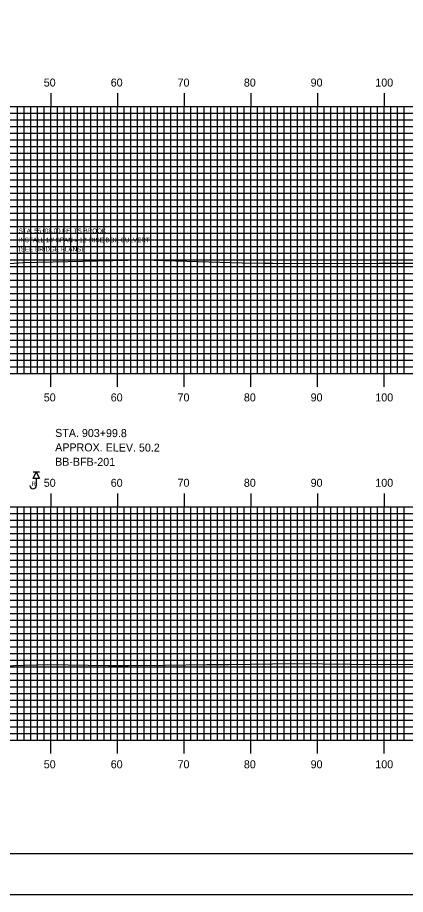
# Model space of a CAD drawing. Extents: x 857110 to 857453, y 364765 to 364985.
# Drawn here: x 857320.8 to 857379, y 364765.2 to 364896.6 of the extents above; entities that cross this region are included whole.
import ezdxf

# ---------------------------------------------------------------- set-up
doc = ezdxf.new("R2010")
doc.units = 0
for name, color, linetype in [('ANNOTATION', 7, 'Continuous'), ('BORDER', 7, 'Continuous'), ('BORING - REFUSAL', 7, 'Continuous'), ('H_V ANNOTATION', 7, 'Continuous'), ('MAJOR', 7, 'Continuous'), ('MINOR', 7, 'Continuous'), ('PLOT BOUNDARY', 7, 'Continuous'), ('S_Roadway_Centerline', 7, 'Continuous')]:
    doc.layers.add(name, color=color, linetype=linetype)

msp = doc.modelspace()

# ---------------------------------------------------------------- linework, layer by layer
at = {"layer": 'BORDER'}
msp.add_lwpolyline([(857126.19, 364771.3), (857446.19, 364771.3), (857446.19, 364981.3), (857126.19, 364981.3)], close=True, dxfattribs=at)
at = {"layer": 'BORING - REFUSAL'}
for p, q in [((857324.07, 364828.5), (857323.11, 364828.5)), ((857323.59, 364827.54), (857323.59, 364826.48))]:
    msp.add_line(p, q, dxfattribs=at)
msp.add_lwpolyline([(857323.59, 364828.5), (857324.07, 364827.54), (857323.11, 364827.54)], close=True, dxfattribs=at)
msp.add_arc((857323.11, 364826.48), 0.485, 180, 0, dxfattribs=at)
at = {"layer": 'MAJOR'}
for p, q in [((857325.79, 364885.31), (857325.79, 364883.3)), ((857335.79, 364885.31), (857335.79, 364883.3)), ((857345.79, 364885.31), (857345.79, 364883.3)), ((857355.79, 364885.31), (857355.79, 364883.3)), ((857365.79, 364885.31), (857365.79, 364883.3)), ((857375.79, 364885.31), (857375.79, 364883.3)), ((857135.79, 364883.3), (857415.79, 364883.3)), ((857135.79, 364883.3), (857415.79, 364883.3)), ((857325.79, 364843.3), (857325.79, 364883.3)), ((857335.79, 364843.3), (857335.79, 364883.3)), ((857345.79, 364843.3), (857345.79, 364883.3)), ((857355.79, 364843.3), (857355.79, 364883.3)), ((857365.79, 364843.3), (857365.79, 364883.3)), ((857375.79, 364843.3), (857375.79, 364883.3)), ((857135.79, 364878.3), (857415.79, 364878.3)), ((857135.79, 364873.3), (857415.79, 364873.3)), ((857135.79, 364868.3), (857415.79, 364868.3)), ((857135.79, 364863.3), (857415.79, 364863.3)), ((857135.79, 364858.3), (857415.79, 364858.3)), ((857135.79, 364853.3), (857415.79, 364853.3)), ((857135.79, 364848.3), (857415.79, 364848.3)), ((857135.79, 364843.3), (857415.79, 364843.3)), ((857135.79, 364843.3), (857415.79, 364843.3)), ((857325.79, 364841.3), (857325.79, 364843.3)), ((857335.79, 364841.3), (857335.79, 364843.3)), ((857345.79, 364841.3), (857345.79, 364843.3)), ((857355.79, 364841.3), (857355.79, 364843.3)), ((857365.79, 364841.3), (857365.79, 364843.3)), ((857375.79, 364841.3), (857375.79, 364843.3)), ((857325.79, 364825.31), (857325.79, 364823.3)), ((857335.79, 364825.31), (857335.79, 364823.3)), ((857345.79, 364825.31), (857345.79, 364823.3)), ((857355.79, 364825.31), (857355.79, 364823.3)), ((857365.79, 364825.31), (857365.79, 364823.3)), ((857375.79, 364825.31), (857375.79, 364823.3)), ((857135.79, 364823.3), (857415.79, 364823.3)), ((857135.79, 364823.3), (857415.79, 364823.3)), ((857325.79, 364788.3), (857325.79, 364823.3)), ((857335.79, 364788.3), (857335.79, 364823.3)), ((857345.79, 364788.3), (857345.79, 364823.3)), ((857355.79, 364788.3), (857355.79, 364823.3)), ((857365.79, 364788.3), (857365.79, 364823.3)), ((857375.79, 364788.3), (857375.79, 364823.3)), ((857135.79, 364818.3), (857415.79, 364818.3)), ((857135.79, 364813.3), (857415.79, 364813.3)), ((857135.79, 364808.3), (857415.79, 364808.3)), ((857135.79, 364803.3), (857415.79, 364803.3)), ((857135.79, 364798.3), (857415.79, 364798.3)), ((857135.79, 364793.3), (857415.79, 364793.3)), ((857135.79, 364788.3), (857415.79, 364788.3)), ((857135.79, 364788.3), (857415.79, 364788.3)), ((857325.79, 364786.3), (857325.79, 364788.3)), ((857335.79, 364786.3), (857335.79, 364788.3)), ((857345.79, 364786.3), (857345.79, 364788.3)), ((857355.79, 364786.3), (857355.79, 364788.3)), ((857365.79, 364786.3), (857365.79, 364788.3)), ((857375.79, 364786.3), (857375.79, 364788.3))]:
    msp.add_line(p, q, dxfattribs=at)
at = {"layer": 'MINOR'}
for p, q in [((857320.79, 364843.3), (857320.79, 364883.3)), ((857321.79, 364843.3), (857321.79, 364883.3)), ((857322.79, 364843.3), (857322.79, 364883.3)), ((857323.79, 364843.3), (857323.79, 364883.3)), ((857324.79, 364843.3), (857324.79, 364883.3)), ((857326.79, 364843.3), (857326.79, 364883.3)), ((857327.79, 364843.3), (857327.79, 364883.3)), ((857328.79, 364843.3), (857328.79, 364883.3)), ((857329.79, 364843.3), (857329.79, 364883.3)), ((857330.79, 364843.3), (857330.79, 364883.3)), ((857331.79, 364843.3), (857331.79, 364883.3)), ((857332.79, 364843.3), (857332.79, 364883.3)), ((857333.79, 364843.3), (857333.79, 364883.3)), ((857334.79, 364843.3), (857334.79, 364883.3)), ((857336.79, 364843.3), (857336.79, 364883.3)), ((857337.79, 364843.3), (857337.79, 364883.3)), ((857338.79, 364843.3), (857338.79, 364883.3)), ((857339.79, 364843.3), (857339.79, 364883.3)), ((857340.79, 364843.3), (857340.79, 364883.3)), ((857341.79, 364843.3), (857341.79, 364883.3)), ((857342.79, 364843.3), (857342.79, 364883.3)), ((857343.79, 364843.3), (857343.79, 364883.3)), ((857344.79, 364843.3), (857344.79, 364883.3)), ((857346.79, 364843.3), (857346.79, 364883.3)), ((857347.79, 364843.3), (857347.79, 364883.3)), ((857348.79, 364843.3), (857348.79, 364883.3)), ((857349.79, 364843.3), (857349.79, 364883.3)), ((857350.79, 364843.3), (857350.79, 364883.3)), ((857351.79, 364843.3), (857351.79, 364883.3)), ((857352.79, 364843.3), (857352.79, 364883.3)), ((857353.79, 364843.3), (857353.79, 364883.3)), ((857354.79, 364843.3), (857354.79, 364883.3)), ((857356.79, 364843.3), (857356.79, 364883.3)), ((857357.79, 364843.3), (857357.79, 364883.3)), ((857358.79, 364843.3), (857358.79, 364883.3)), ((857359.79, 364843.3), (857359.79, 364883.3)), ((857360.79, 364843.3), (857360.79, 364883.3)), ((857361.79, 364843.3), (857361.79, 364883.3)), ((857362.79, 364843.3), (857362.79, 364883.3)), ((857363.79, 364843.3), (857363.79, 364883.3)), ((857364.79, 364843.3), (857364.79, 364883.3)), ((857366.79, 364843.3), (857366.79, 364883.3)), ((857367.79, 364843.3), (857367.79, 364883.3)), ((857368.79, 364843.3), (857368.79, 364883.3)), ((857369.79, 364843.3), (857369.79, 364883.3)), ((857370.79, 364843.3), (857370.79, 364883.3)), ((857371.79, 364843.3), (857371.79, 364883.3)), ((857372.79, 364843.3), (857372.79, 364883.3)), ((857373.79, 364843.3), (857373.79, 364883.3)), ((857374.79, 364843.3), (857374.79, 364883.3)), ((857376.79, 364843.3), (857376.79, 364883.3)), ((857377.79, 364843.3), (857377.79, 364883.3)), ((857378.79, 364843.3), (857378.79, 364883.3)), ((857135.79, 364882.3), (857415.79, 364882.3)), ((857135.79, 364881.3), (857415.79, 364881.3)), ((857135.79, 364880.3), (857415.79, 364880.3)), ((857135.79, 364879.3), (857415.79, 364879.3)), ((857135.79, 364877.3), (857415.79, 364877.3)), ((857135.79, 364876.3), (857415.79, 364876.3)), ((857135.79, 364875.3), (857415.79, 364875.3)), ((857135.79, 364874.3), (857415.79, 364874.3)), ((857135.79, 364872.3), (857415.79, 364872.3)), ((857135.79, 364871.3), (857415.79, 364871.3)), ((857135.79, 364870.3), (857415.79, 364870.3)), ((857135.79, 364869.3), (857415.79, 364869.3)), ((857135.79, 364867.3), (857415.79, 364867.3)), ((857135.79, 364866.3), (857415.79, 364866.3)), ((857135.79, 364865.3), (857415.79, 364865.3)), ((857135.79, 364864.3), (857415.79, 364864.3)), ((857135.79, 364862.3), (857415.79, 364862.3)), ((857135.79, 364861.3), (857415.79, 364861.3)), ((857135.79, 364860.3), (857415.79, 364860.3)), ((857135.79, 364859.3), (857415.79, 364859.3)), ((857135.79, 364857.3), (857415.79, 364857.3)), ((857135.79, 364856.3), (857415.79, 364856.3)), ((857135.79, 364855.3), (857415.79, 364855.3)), ((857135.79, 364854.3), (857415.79, 364854.3)), ((857135.79, 364852.3), (857415.79, 364852.3)), ((857135.79, 364851.3), (857415.79, 364851.3)), ((857135.79, 364850.3), (857415.79, 364850.3)), ((857135.79, 364849.3), (857415.79, 364849.3)), ((857135.79, 364847.3), (857415.79, 364847.3)), ((857135.79, 364846.3), (857415.79, 364846.3)), ((857135.79, 364845.3), (857415.79, 364845.3)), ((857135.79, 364844.3), (857415.79, 364844.3)), ((857135.79, 364822.3), (857415.79, 364822.3)), ((857320.79, 364788.3), (857320.79, 364823.3)), ((857321.79, 364788.3), (857321.79, 364823.3)), ((857322.79, 364788.3), (857322.79, 364823.3)), ((857323.79, 364788.3), (857323.79, 364823.3)), ((857324.79, 364788.3), (857324.79, 364823.3)), ((857326.79, 364788.3), (857326.79, 364823.3)), ((857327.79, 364788.3), (857327.79, 364823.3)), ((857328.79, 364788.3), (857328.79, 364823.3)), ((857329.79, 364788.3), (857329.79, 364823.3)), ((857330.79, 364788.3), (857330.79, 364823.3)), ((857331.79, 364788.3), (857331.79, 364823.3)), ((857332.79, 364788.3), (857332.79, 364823.3)), ((857333.79, 364788.3), (857333.79, 364823.3)), ((857334.79, 364788.3), (857334.79, 364823.3)), ((857336.79, 364788.3), (857336.79, 364823.3)), ((857337.79, 364788.3), (857337.79, 364823.3)), ((857338.79, 364788.3), (857338.79, 364823.3)), ((857339.79, 364788.3), (857339.79, 364823.3)), ((857340.79, 364788.3), (857340.79, 364823.3)), ((857341.79, 364788.3), (857341.79, 364823.3)), ((857342.79, 364788.3), (857342.79, 364823.3)), ((857343.79, 364788.3), (857343.79, 364823.3)), ((857344.79, 364788.3), (857344.79, 364823.3)), ((857346.79, 364788.3), (857346.79, 364823.3)), ((857347.79, 364788.3), (857347.79, 364823.3)), ((857348.79, 364788.3), (857348.79, 364823.3)), ((857349.79, 364788.3), (857349.79, 364823.3)), ((857350.79, 364788.3), (857350.79, 364823.3)), ((857351.79, 364788.3), (857351.79, 364823.3)), ((857352.79, 364788.3), (857352.79, 364823.3)), ((857353.79, 364788.3), (857353.79, 364823.3)), ((857354.79, 364788.3), (857354.79, 364823.3)), ((857356.79, 364788.3), (857356.79, 364823.3)), ((857357.79, 364788.3), (857357.79, 364823.3)), ((857358.79, 364788.3), (857358.79, 364823.3)), ((857359.79, 364788.3), (857359.79, 364823.3)), ((857360.79, 364788.3), (857360.79, 364823.3)), ((857361.79, 364788.3), (857361.79, 364823.3)), ((857362.79, 364788.3), (857362.79, 364823.3)), ((857363.79, 364788.3), (857363.79, 364823.3)), ((857364.79, 364788.3), (857364.79, 364823.3)), ((857366.79, 364788.3), (857366.79, 364823.3)), ((857367.79, 364788.3), (857367.79, 364823.3)), ((857368.79, 364788.3), (857368.79, 364823.3)), ((857369.79, 364788.3), (857369.79, 364823.3)), ((857370.79, 364788.3), (857370.79, 364823.3)), ((857371.79, 364788.3), (857371.79, 364823.3)), ((857372.79, 364788.3), (857372.79, 364823.3)), ((857373.79, 364788.3), (857373.79, 364823.3)), ((857374.79, 364788.3), (857374.79, 364823.3)), ((857376.79, 364788.3), (857376.79, 364823.3)), ((857377.79, 364788.3), (857377.79, 364823.3)), ((857378.79, 364788.3), (857378.79, 364823.3)), ((857135.79, 364821.3), (857415.79, 364821.3)), ((857135.79, 364820.3), (857415.79, 364820.3)), ((857135.79, 364819.3), (857415.79, 364819.3)), ((857135.79, 364817.3), (857415.79, 364817.3)), ((857135.79, 364816.3), (857415.79, 364816.3)), ((857135.79, 364815.3), (857415.79, 364815.3)), ((857135.79, 364814.3), (857415.79, 364814.3)), ((857135.79, 364812.3), (857415.79, 364812.3)), ((857135.79, 364811.3), (857415.79, 364811.3)), ((857135.79, 364810.3), (857415.79, 364810.3)), ((857135.79, 364809.3), (857415.79, 364809.3)), ((857135.79, 364807.3), (857415.79, 364807.3)), ((857135.79, 364806.3), (857415.79, 364806.3)), ((857135.79, 364805.3), (857415.79, 364805.3)), ((857135.79, 364804.3), (857415.79, 364804.3)), ((857135.79, 364802.3), (857415.79, 364802.3)), ((857135.79, 364801.3), (857415.79, 364801.3)), ((857135.79, 364800.3), (857415.79, 364800.3)), ((857135.79, 364799.3), (857415.79, 364799.3)), ((857135.79, 364797.3), (857415.79, 364797.3)), ((857135.79, 364796.3), (857415.79, 364796.3)), ((857135.79, 364795.3), (857415.79, 364795.3)), ((857135.79, 364794.3), (857415.79, 364794.3)), ((857135.79, 364792.3), (857415.79, 364792.3)), ((857135.79, 364791.3), (857415.79, 364791.3)), ((857135.79, 364790.3), (857415.79, 364790.3)), ((857135.79, 364789.3), (857415.79, 364789.3))]:
    msp.add_line(p, q, dxfattribs=at)
at = {"layer": 'PLOT BOUNDARY'}
msp.add_lwpolyline([(857110.01, 364765.18), (857450.01, 364765.18), (857450.01, 364985.18), (857110.01, 364985.18)], close=True, dxfattribs=at)
at = {"layer": 'S_Roadway_Centerline'}
for points in [[(857305.39, 364858.78), (857320.95, 364859.89), (857321.58, 364859.9), (857339.57, 364860.34), (857354.51, 364859.89), (857357.85, 364859.8), (857359.08, 364859.8), (857361.86, 364859.78), (857375.05, 364859.83), (857383.56, 364859.84), (857393.24, 364859.93), (857396.16, 364860.02), (857404.57, 364860.02), (857409.54, 364860), (857411.24, 364859.98), (857415.13, 364860.01), (857415.79, 364860.02)], [(857316.68, 364799.43), (857325.33, 364799.67), (857334.44, 364799.52), (857337.4, 364799.51), (857342.96, 364799.57), (857349.21, 364799.66), (857352.55, 364799.65), (857362.29, 364799.83), (857370.85, 364799.69), (857378.51, 364799.66), (857390.01, 364799.88), (857399.29, 364799.73), (857408.36, 364799.74), (857415.79, 364799.63)]]:
    msp.add_lwpolyline(points, dxfattribs=at)

# ---------------------------------------------------------------- texts
at = {"layer": 'ANNOTATION'}
for s, p in [('STA. 55+08.00 FELTS BROOK', (857320.95, 364864.34)), ("INSTALL 18' SPAN x 12' RISE BOX CULVERT", (857320.95, 364862.96)), ('(SEE BRIDGE PLANS)', (857320.95, 364861.58))]:
    msp.add_text(s, height=0.68, dxfattribs=at).set_placement(p)
at = {"layer": 'BORING - REFUSAL'}
for s, p in [('STA. 903+99.8', (857326.43, 364833.78)), ('APPROX. ELEV. 50.2', (857326.43, 364831.62)), ('BB-BFB-201', (857326.42, 364829.46))]:
    msp.add_text(s, height=1.2, rotation=359.8142, dxfattribs=at).set_placement(p)
msp.add_text('R', height=0.64, dxfattribs=at).set_placement((857322.89, 364826.43))
at = {"layer": 'H_V ANNOTATION'}
for s, p in [('50', (857324.72, 364886.3)), ('60', (857334.77, 364886.3)), ('70', (857344.8, 364886.3)), ('80', (857354.75, 364886.3)), ('90', (857364.77, 364886.3)), ('100', (857374.48, 364886.3)), ('50', (857324.72, 364839.1)), ('60', (857334.77, 364839.1)), ('70', (857344.8, 364839.1)), ('80', (857354.75, 364839.1)), ('90', (857364.77, 364839.1)), ('100', (857374.48, 364839.1)), ('50', (857324.72, 364826.3)), ('60', (857334.77, 364826.3)), ('70', (857344.8, 364826.3)), ('80', (857354.75, 364826.3)), ('90', (857364.77, 364826.3)), ('100', (857374.48, 364826.3)), ('50', (857324.72, 364784.1)), ('60', (857334.77, 364784.1)), ('70', (857344.8, 364784.1)), ('80', (857354.75, 364784.1)), ('90', (857364.77, 364784.1)), ('100', (857374.48, 364784.1))]:
    msp.add_text(s, height=1.2, dxfattribs=at).set_placement(p)

doc.saveas('drawing.dxf')
